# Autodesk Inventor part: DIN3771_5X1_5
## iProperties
Created: 2007-03
Part Number: DIN3771_5X1_5
Document SubType Name: Modeling
Designer: Andy Moles
Material: Rubber
Mass: 0.0335597 g
Surface Area: 0.962286 cm^2
Volume: 0.0360857 cm^3
Density: 0.93 g/cm^3
Author: Andy Moles
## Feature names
1. Base1
